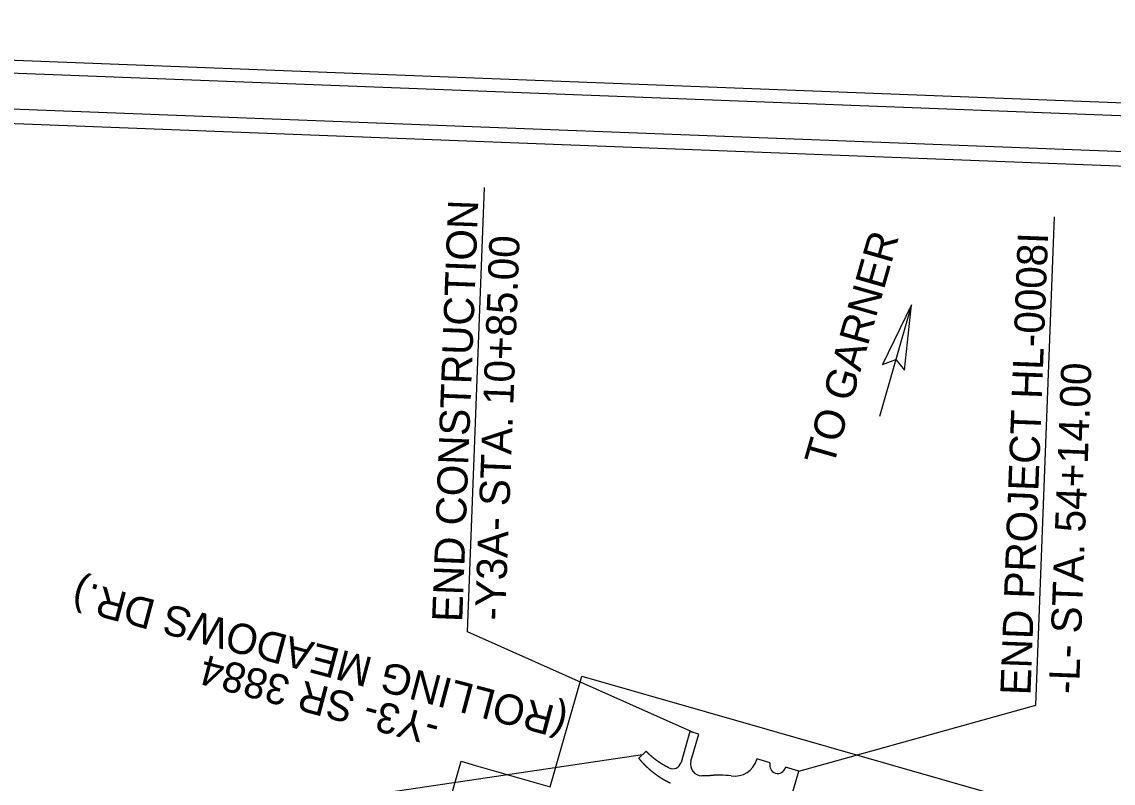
# Model space of a CAD drawing. Extents: x 2094564 to 2100382, y 679033 to 692366.
# Drawn here: x 2096651 to 2098550, y 689379 to 690703 of the extents above; entities that cross this region are included whole.
import ezdxf

# ---------------------------------------------------------------- set-up
doc = ezdxf.new("R2010")
doc.units = 0
for name, color, linetype in [('Exist Horizontal Alignment', 7, 'Continuous'), ('Pattern 17', 7, 'Continuous'), ('Prop Horizontal Alignment', 7, 'Continuous'), ('Prop Horizontal Alignment Direction Label', 7, 'Continuous'), ('Prop Horizontal Alignment Tick Label', 7, 'Continuous'), ('Prop Horizontal Alignment Tick Large', 7, 'Continuous'), ('Prop Shade Light', 7, 'Continuous'), ('Scratch_Level_0', 7, 'Continuous')]:
    doc.layers.add(name, color=color, linetype=linetype)

msp = doc.modelspace()

# ---------------------------------------------------------------- linework, layer by layer
at = {"layer": 'Exist Horizontal Alignment'}
msp.add_lwpolyline([(2098187.13831813, 690097.1121085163), (2098199.2175029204, 690210.5660347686), (2098149.109835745, 690107.2588733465), (2098172.2629947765, 690115.6208647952)], close=True, dxfattribs=at)
at = {"layer": 'Pattern 17'}
msp.add_lwpolyline([(2098117.795764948, 688054.4934181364), (2097347.7255769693, 688084.0267354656), (2097057.8315694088, 688167.010765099), (2097360.525098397, 689224.4315792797), (2097415.581689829, 689416.7646824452), (2097440.823837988, 689409.5389547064), (2097570.412928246, 689372.4432416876), (2097625.467285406, 689564.7685397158), (2098480.091497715, 689320.1268461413)], close=True, dxfattribs=at)
at = {"layer": 'Prop Horizontal Alignment'}
msp.add_line((2098199.2175029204, 690210.5660347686), (2098143.755135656, 690016.81540605), dxfattribs=at)
at = {"layer": 'Prop Horizontal Alignment Direction Label'}
for points in [[(2100204.3119824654, 690414.1031092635), (2095058.1576628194, 690611.4656495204)], [(2099254.1142310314, 690425.5262032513), (2095082.1187613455, 690585.5283276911)]]:
    msp.add_lwpolyline(points, dxfattribs=at)
at = {"layer": 'Prop Horizontal Alignment Tick Label'}
msp.add_lwpolyline([(2099950.1447445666, 682147.7711279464), (2100269.4735454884, 690474.1500147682), (2094997.8489649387, 690676.32452293), (2094678.5201640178, 682349.9456361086)], close=True, dxfattribs=at)
at = {"layer": 'Prop Horizontal Alignment Tick Large'}
msp.add_lwpolyline([(2094886.5436985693, 690703.1097833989), (2094563.8616099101, 682289.2951746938), (2100059.7588170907, 682078.5194834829), (2100382.4409057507, 690492.334092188)], close=True, dxfattribs=at)
at = {"layer": 'Prop Shade Light'}
for p, q in [((2097813.7187364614, 689468.3634568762), (2097798.338539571, 689414.6347221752)), ((2097829.100914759, 689463.9602091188), (2097813.7187364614, 689468.3634568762)), ((2097815.6192545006, 689416.863767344), (2097829.100914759, 689463.9602091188)), ((2097737.645297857, 689434.2168121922), (2097724.6720181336, 689422.1232874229)), ((2097930.269659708, 689420.8210109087), (2097929.9900349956, 689419.8441780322)), ((2097953.342927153, 689414.2161392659), (2097930.269659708, 689420.8210109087)), ((2097953.136547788, 689413.4951795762), (2097953.342927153, 689414.2161392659)), ((2097906.980912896, 689063.3049817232), (2098003.3350066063, 689399.9055840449)), ((2097980.25966301, 689406.5032029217), (2097980.0553598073, 689405.7894959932)), ((2098003.3350066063, 689399.9055840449), (2097980.25966301, 689406.5032029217))]:
    msp.add_line(p, q, dxfattribs=at)
for centre, radius, start, end in [((2097783.9177474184, 689418.7627669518), 15.000000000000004, 243.99730906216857, 344.02588888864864), ((2097834.846976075, 689411.3597031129), 20.000000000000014, 164.02587539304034, 268.56416981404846), ((2097891.534589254, 689430.8522974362), 40.00000000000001, 261.7881959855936, 344.02588888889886), ((2097966.595953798, 689409.6423377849), 13.999999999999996, 164.025888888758, 344.02588888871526), ((2097862.2538563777, 689227.9541981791), 165.00000000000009, 81.78819598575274, 88.42085888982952)]:
    msp.add_arc(centre, radius, start, end, dxfattribs=at)
for points in [[(2097749.11018101, 689423.5735609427), (2097748.9692910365, 689423.6913340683), (2097748.484999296, 689424.098565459), (2097748.0024577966, 689424.5080565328), (2097747.5216770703, 689424.9197997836), (2097747.042667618, 689425.3337876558), (2097746.565439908, 689425.7500125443), (2097746.090004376, 689426.1684667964), (2097745.616371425, 689426.5891427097), (2097745.1445514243, 689427.0120325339), (2097744.6745547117, 689427.4371284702), (2097744.2063915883, 689427.8644226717), (2097743.7400723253, 689428.2939072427), (2097743.275607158, 689428.7255742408), (2097742.8130062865, 689429.1594156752), (2097742.352279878, 689429.5954235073), (2097741.8934380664, 689430.0335896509), (2097741.436490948, 689430.4739059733), (2097740.9814485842, 689430.916364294), (2097740.5277918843, 689431.3615232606), (2097740.0473762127, 689431.8374047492), (2097739.566960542, 689432.3132862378), (2097739.086544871, 689432.7891677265), (2097738.6061291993, 689433.2650492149), (2097737.645297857, 689434.2168121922)], [(2097724.6720181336, 689422.1232874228), (2097725.552030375, 689421.0961859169), (2097725.9920364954, 689420.5826351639), (2097726.4320426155, 689420.069084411), (2097726.8720487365, 689419.555533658), (2097727.312054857, 689419.0419829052), (2097727.7800511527, 689418.5006823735), (2097728.2510819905, 689417.9608560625), (2097728.7246277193, 689417.42306464), (2097729.200679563, 689416.8873198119), (2097729.679228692, 689416.3536332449), (2097730.1602662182, 689415.8220165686), (2097730.6437832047, 689415.292481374), (2097731.1297706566, 689414.7650392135), (2097731.6182195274, 689414.2397016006), (2097732.109120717, 689413.7164800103), (2097732.60246507, 689413.1953858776), (2097733.09824338, 689412.6764305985), (2097733.5964463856, 689412.1596255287), (2097734.0970647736, 689411.6449819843), (2097734.6000891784, 689411.132511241), (2097735.105510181, 689410.622224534), (2097735.6133183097, 689410.1141330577), (2097736.123504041, 689409.6082479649), (2097736.633836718, 689409.1067531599)], [(2097761.6589886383, 689414.2361393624), (2097761.6139743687, 689414.2658834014), (2097761.0894389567, 689414.6143291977), (2097760.566380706, 689414.9652060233), (2097760.044810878, 689415.3185076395), (2097759.524740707, 689415.6742277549), (2097759.006181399, 689416.0323600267), (2097758.489144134, 689416.3928980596), (2097757.973640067, 689416.7558354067), (2097757.459680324, 689417.1211655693), (2097756.9472760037, 689417.4888819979), (2097756.4364381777, 689417.8589780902), (2097755.9271778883, 689418.2314471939), (2097755.4195061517, 689418.6062826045), (2097754.913433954, 689418.9834775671), (2097754.4089722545, 689419.3630252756), (2097753.9061319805, 689419.7449188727), (2097753.4049240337, 689420.1291514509), (2097752.9053592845, 689420.5157160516), (2097752.4074485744, 689420.9046056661), (2097751.9112027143, 689421.2958132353), (2097751.416632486, 689421.6893316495), (2097750.923748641, 689422.0851537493), (2097750.4325618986, 689422.4832723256), (2097749.94308295, 689422.8836801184), (2097749.4553224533, 689423.2863698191), (2097749.11018101, 689423.5735609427)], [(2097775.173993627, 689406.3619926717), (2097774.6162604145, 689406.6477896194), (2097774.059715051, 689406.9361563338), (2097773.5043693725, 689407.227087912), (2097772.950235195, 689407.5205793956), (2097772.3973243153, 689407.8166257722), (2097771.845648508, 689408.1152219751), (2097771.295219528, 689408.4163628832), (2097770.7460491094, 689408.7200433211), (2097770.198148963, 689409.0262580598), (2097769.651530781, 689409.3350018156), (2097769.1062062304, 689409.6462692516), (2097768.56218696, 689409.9600549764), (2097768.0194845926, 689410.2763535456), (2097767.4781107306, 689410.5951594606), (2097766.9380769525, 689410.9164671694), (2097766.399394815, 689411.2402710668), (2097765.862075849, 689411.566565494), (2097765.326131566, 689411.8953447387), (2097764.7915734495, 689412.226603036), (2097764.258412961, 689412.5603345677), (2097763.726661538, 689412.8965334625), (2097763.196330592, 689413.2351937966), (2097762.667431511, 689413.5763095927), (2097762.1399756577, 689413.9198748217), (2097761.6589886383, 689414.2361393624)], [(2097736.633836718, 689409.1067531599), (2097736.6360578, 689409.1045803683), (2097737.1509699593, 689408.6031413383), (2097737.66823084, 689408.1039419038), (2097738.187830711, 689407.6069930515), (2097738.7097597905, 689407.1123057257), (2097739.234008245, 689406.6198908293), (2097739.7605661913, 689406.1297592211), (2097740.2894236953, 689405.6419217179), (2097740.8205707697, 689405.1563890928), (2097741.3539973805, 689404.673172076), (2097741.8896934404, 689404.1922813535), (2097742.4276488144, 689403.7137275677), (2097742.967853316, 689403.2375213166), (2097743.5102967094, 689402.7636731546), (2097744.0549687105, 689402.2921935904), (2097744.601858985, 689401.8230930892), (2097745.150957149, 689401.3563820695), (2097745.702252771, 689400.8920709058), (2097746.25573537, 689400.4301699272), (2097746.811394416, 689399.9706894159), (2097747.3692193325, 689399.5136396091), (2097747.9291994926, 689399.0590306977), (2097748.4913242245, 689398.6068728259), (2097749.055582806, 689398.1571760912), (2097749.621964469, 689397.7099505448), (2097749.9348608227, 689397.4646539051)], [(2097749.9348608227, 689397.4646539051), (2097750.1904583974, 689397.2652061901), (2097750.7610537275, 689396.8229529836), (2097751.3337395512, 689396.3832008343), (2097751.9085049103, 689395.9459596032), (2097752.485338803, 689395.5112391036), (2097753.0642301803, 689395.0790491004), (2097753.6451679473, 689394.6493993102), (2097754.2281409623, 689394.2222994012), (2097754.813138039, 689393.7977589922), (2097755.4001479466, 689393.3757876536), (2097755.9891594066, 689392.9563949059), (2097756.5801610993, 689392.5395902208), (2097757.1731416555, 689392.1253830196), (2097757.768089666, 689391.7137826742), (2097758.364993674, 689391.3047985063), (2097758.963842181, 689390.8984397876), (2097759.564623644, 689390.4947157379), (2097760.1673264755, 689390.0936355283), (2097760.7719390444, 689389.6952082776), (2097761.378449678, 689389.2994430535), (2097761.9868466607, 689388.9063488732), (2097762.5971182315, 689388.5159347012), (2097763.2092525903, 689388.1282094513), (2097763.823237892, 689387.7431819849), (2097764.439062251, 689387.360861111)], [(2097777.341547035, 689405.2811650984), (2097776.8542016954, 689405.520068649), (2097776.2929761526, 689405.7981274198), (2097775.7329028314, 689406.0787703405), (2097775.173993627, 689406.3619926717)], [(2097764.439062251, 689387.360861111), (2097765.0567137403, 689386.9812555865), (2097765.676180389, 689386.6043741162), (2097766.297450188, 689386.2302253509), (2097766.9205110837, 689385.8588178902), (2097767.5453509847, 689385.4901602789), (2097768.1719577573, 689385.1242610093), (2097768.8003192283, 689384.7611285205), (2097769.4304231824, 689384.4007711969), (2097770.062257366, 689384.04319737), (2097770.6958094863, 689383.6884153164), (2097771.3310672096, 689383.3364332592), (2097771.968018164, 689382.9872593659), (2097772.6066499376, 689382.6409017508), (2097773.2469500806, 689382.2973684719), (2097773.888906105, 689381.9566675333), (2097774.532505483, 689381.6188068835), (2097775.177735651, 689381.2837944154), (2097775.8245840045, 689380.9516379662), (2097776.4730379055, 689380.6223453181), (2097777.1230846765, 689380.2959241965), (2097777.7747116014, 689379.9723822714), (2097778.4279059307, 689379.6517271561), (2097779.0826548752, 689379.3339664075), (2097779.7389456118, 689379.0191075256), (2097780.2474394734, 689378.7776521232)], [(2097850.580038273, 689391.9523974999), (2097850.1551788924, 689391.9121623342), (2097849.54613618, 689391.856838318), (2097848.9367292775, 689391.8042531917), (2097848.3269705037, 689391.7544091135), (2097847.7168721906, 689391.7073081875), (2097847.106446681, 689391.6629524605), (2097846.4957063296, 689391.6213439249), (2097845.884663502, 689391.5824845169), (2097845.2733305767, 689391.5463761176), (2097844.66171994, 689391.5130205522), (2097844.049843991, 689391.4824195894), (2097843.4377151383, 689391.4545749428), (2097842.8253458, 689391.4294882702), (2097842.2127484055, 689391.407161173), (2097841.5999353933, 689391.3875951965), (2097840.98691921, 689391.3707918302), (2097840.373712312, 689391.3567525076), (2097839.7603271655, 689391.3454786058), (2097839.1467762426, 689391.3369714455), (2097838.5330720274, 689391.3312322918), (2097837.9192270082, 689391.3282623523), (2097837.305253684, 689391.3280627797), (2097836.69116456, 689391.3306346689), (2097836.076972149, 689391.3359790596), (2097835.46268897, 689391.3440969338), (2097834.8483275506, 689391.354989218), (2097834.345828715, 689391.3659603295)], [(2097866.800880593, 689392.8915334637), (2097866.0572553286, 689392.8834273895), (2097865.313795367, 689392.8719692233), (2097864.5705158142, 689392.8571602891), (2097863.82743177, 689392.83900198), (2097863.0845583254, 689392.8174957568), (2097862.341910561, 689392.7926431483), (2097861.599503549, 689392.7644457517), (2097860.8573523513, 689392.7329052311), (2097860.11547202, 689392.6980233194), (2097859.373877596, 689392.6598018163), (2097858.63258411, 689392.6182425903), (2097857.891606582, 689392.5733475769), (2097857.1509600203, 689392.525118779), (2097856.4106594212, 689392.473558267), (2097855.6707197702, 689392.4186681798), (2097854.9311560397, 689392.3604507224), (2097854.191983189, 689392.2989081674), (2097853.453216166, 689392.2340428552), (2097852.7148699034, 689392.1658571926), (2097851.979998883, 689392.094545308), (2097851.372122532, 689392.031018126), (2097850.763845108, 689391.9702230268), (2097850.580038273, 689391.9523974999)]]:
    msp.add_spline(points, degree=3, dxfattribs=at)
at = {"layer": 'Scratch_Level_0'}
for p, q in [((2097426.509466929, 689641.7869017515), (2097456.1509859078, 690414.6784075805)), ((2098415.5974642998, 689514.5474654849), (2098448.1795331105, 690364.1127068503)), ((2097821.40982561, 689466.1618329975), (2097426.509466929, 689641.7869017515)), ((2098003.3350066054, 689399.905584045), (2098415.5974642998, 689514.5474654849)), ((2097731.158657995, 689428.1700498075), (2096802.7983586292, 689290.7816695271))]:
    msp.add_line(p, q, dxfattribs=at)

# ---------------------------------------------------------------- texts
for s, height, rotation, p in [('END CONSTRUCTION', 52.59073265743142, 87.80369948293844, (2097417.423072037, 689658.3429506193)), ('-Y3A- STA. 10+85.00', 52.59073265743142, 87.80369948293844, (2097491.9615616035, 689660.8000132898)), ('TO GARNER', 52.56259578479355, 74.0258888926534, (2098063.026412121, 689927.8021838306)), ('END PROJECT HL-0008I', 52.59073265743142, 87.80369948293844, (2098406.5110694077, 689531.1035143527)), ('-L- STA. 54+14.00', 52.59073265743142, 87.80369948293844, (2098490.771080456, 689533.1877424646)), ('(ROLLING MEADOWS DR.)', 52.562595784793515, 165.16849505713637, (2097603.923969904, 689506.2384077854)), ('-Y3- SR 3884', 52.562595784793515, 165.16849505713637, (2097381.6737053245, 689493.8105948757))]:
    msp.add_text(s, height=height, rotation=rotation, dxfattribs=at).set_placement(p)

doc.saveas('drawing.dxf')
